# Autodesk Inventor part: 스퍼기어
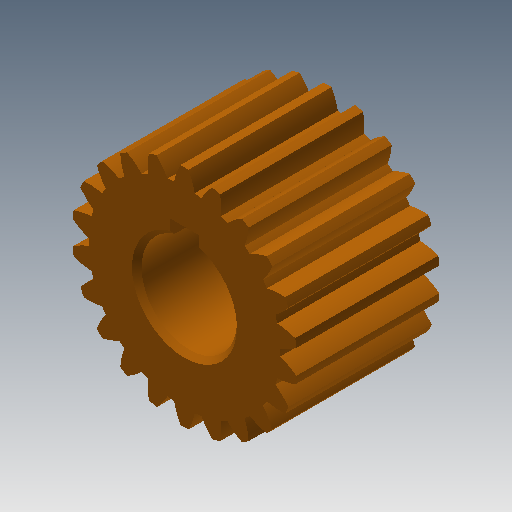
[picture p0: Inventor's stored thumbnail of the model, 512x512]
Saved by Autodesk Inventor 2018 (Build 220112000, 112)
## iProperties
Created: 2019-03
Part Number: 스퍼기어
Material: 강철
Document SubType Name: Modeling
Designer: mduedu
Categories: <?xml version="1.0" encoding="UTF-16"?> <MemberInstance><Categories><FamilyTemplate><FamilyTemplateParameter ValueType="xs:double" Id="1" ObjectReferenceKey="da
Density: 1 g/cm^3
Appearance: 주황색
CustomPartVersion: 1
Author: mduedu
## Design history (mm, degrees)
sketch "Sketch1"
  geometry: C1 r 23.6 at (0, 0)
  constraints: 1 centre point
  dimensions: "d0" = 47.2 diameter of C1 (= da_da)
extrude "Extrusion1" new body sketch "Sketch1" distance "d1" = 30 (= da_b); taper "d2" = 0 deg
workplane "Work Plane2"
sketch "Sketch2"
  geometry: C1 r 23.6 at (0, 0) reference; C2 r 22 at (0, 0)
  constraints: 1 centre point, 1 coincident
  dimensions: "d3" = 44 diameter of C2 (= da_dw)
feature "피치 지름" sketch "Sketch2" dims "d4" = 10, "d5" = 0
workplane "Work Plane8"
workplane "Work Plane9"
feature "스퍼 기어" dims "da_b" = 30, "da_d" = 44, "da_aw" = 44, "da_da" = 47.2, "da_df" = 40.172, "da_dw" = 44, angle "da_beta" = 0 deg, "da_lefttooth" = 0, "da_righttooth" = 0
sketch "스케치3"
  geometry: L1 (-3, 9.539)-(3, 9.539); L2 (3, 9.539)-(3, 12.8); L3 (3, 12.8)-(-3, 12.8); L4 (-3, 12.8)-(-3, 9.539); A1 r 10 centre (0, 0) between (-3, 9.539) and (3, 9.539); 1 further point
  constraints: 8 end point, 2 parallel, 2 point on circle, 1 centre point, 1 coincident, 1 horizontal, 1 perpendicular
  dimensions: "d49" = 20 diameter of A1; "d50" = 6 distance of L2.end L3.end; "d51" = 22.8 dimension on A1 L3
extrude "돌출2" cut sketch "스케치3" extent not by distance; stored distance "d52" = 10; taper "d53" = 0 deg
chamfer "모따기1" distance "d54" = 1; stored, may be unused: second distance "d55" = 2, angle "d56" = 45 deg
body "Solid1"
body "Srf1"
other parameters: "d16" = 44 (= da_aw), "d17" = 0, "d34" = 1.428 (computed from da_z), "d39" = 0, "d41" = 0, "d43" = 44 (= da_aw), "d46" = 44 (= da_aw), "d47" = 0, "d48" = 0
